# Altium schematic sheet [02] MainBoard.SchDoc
size A3
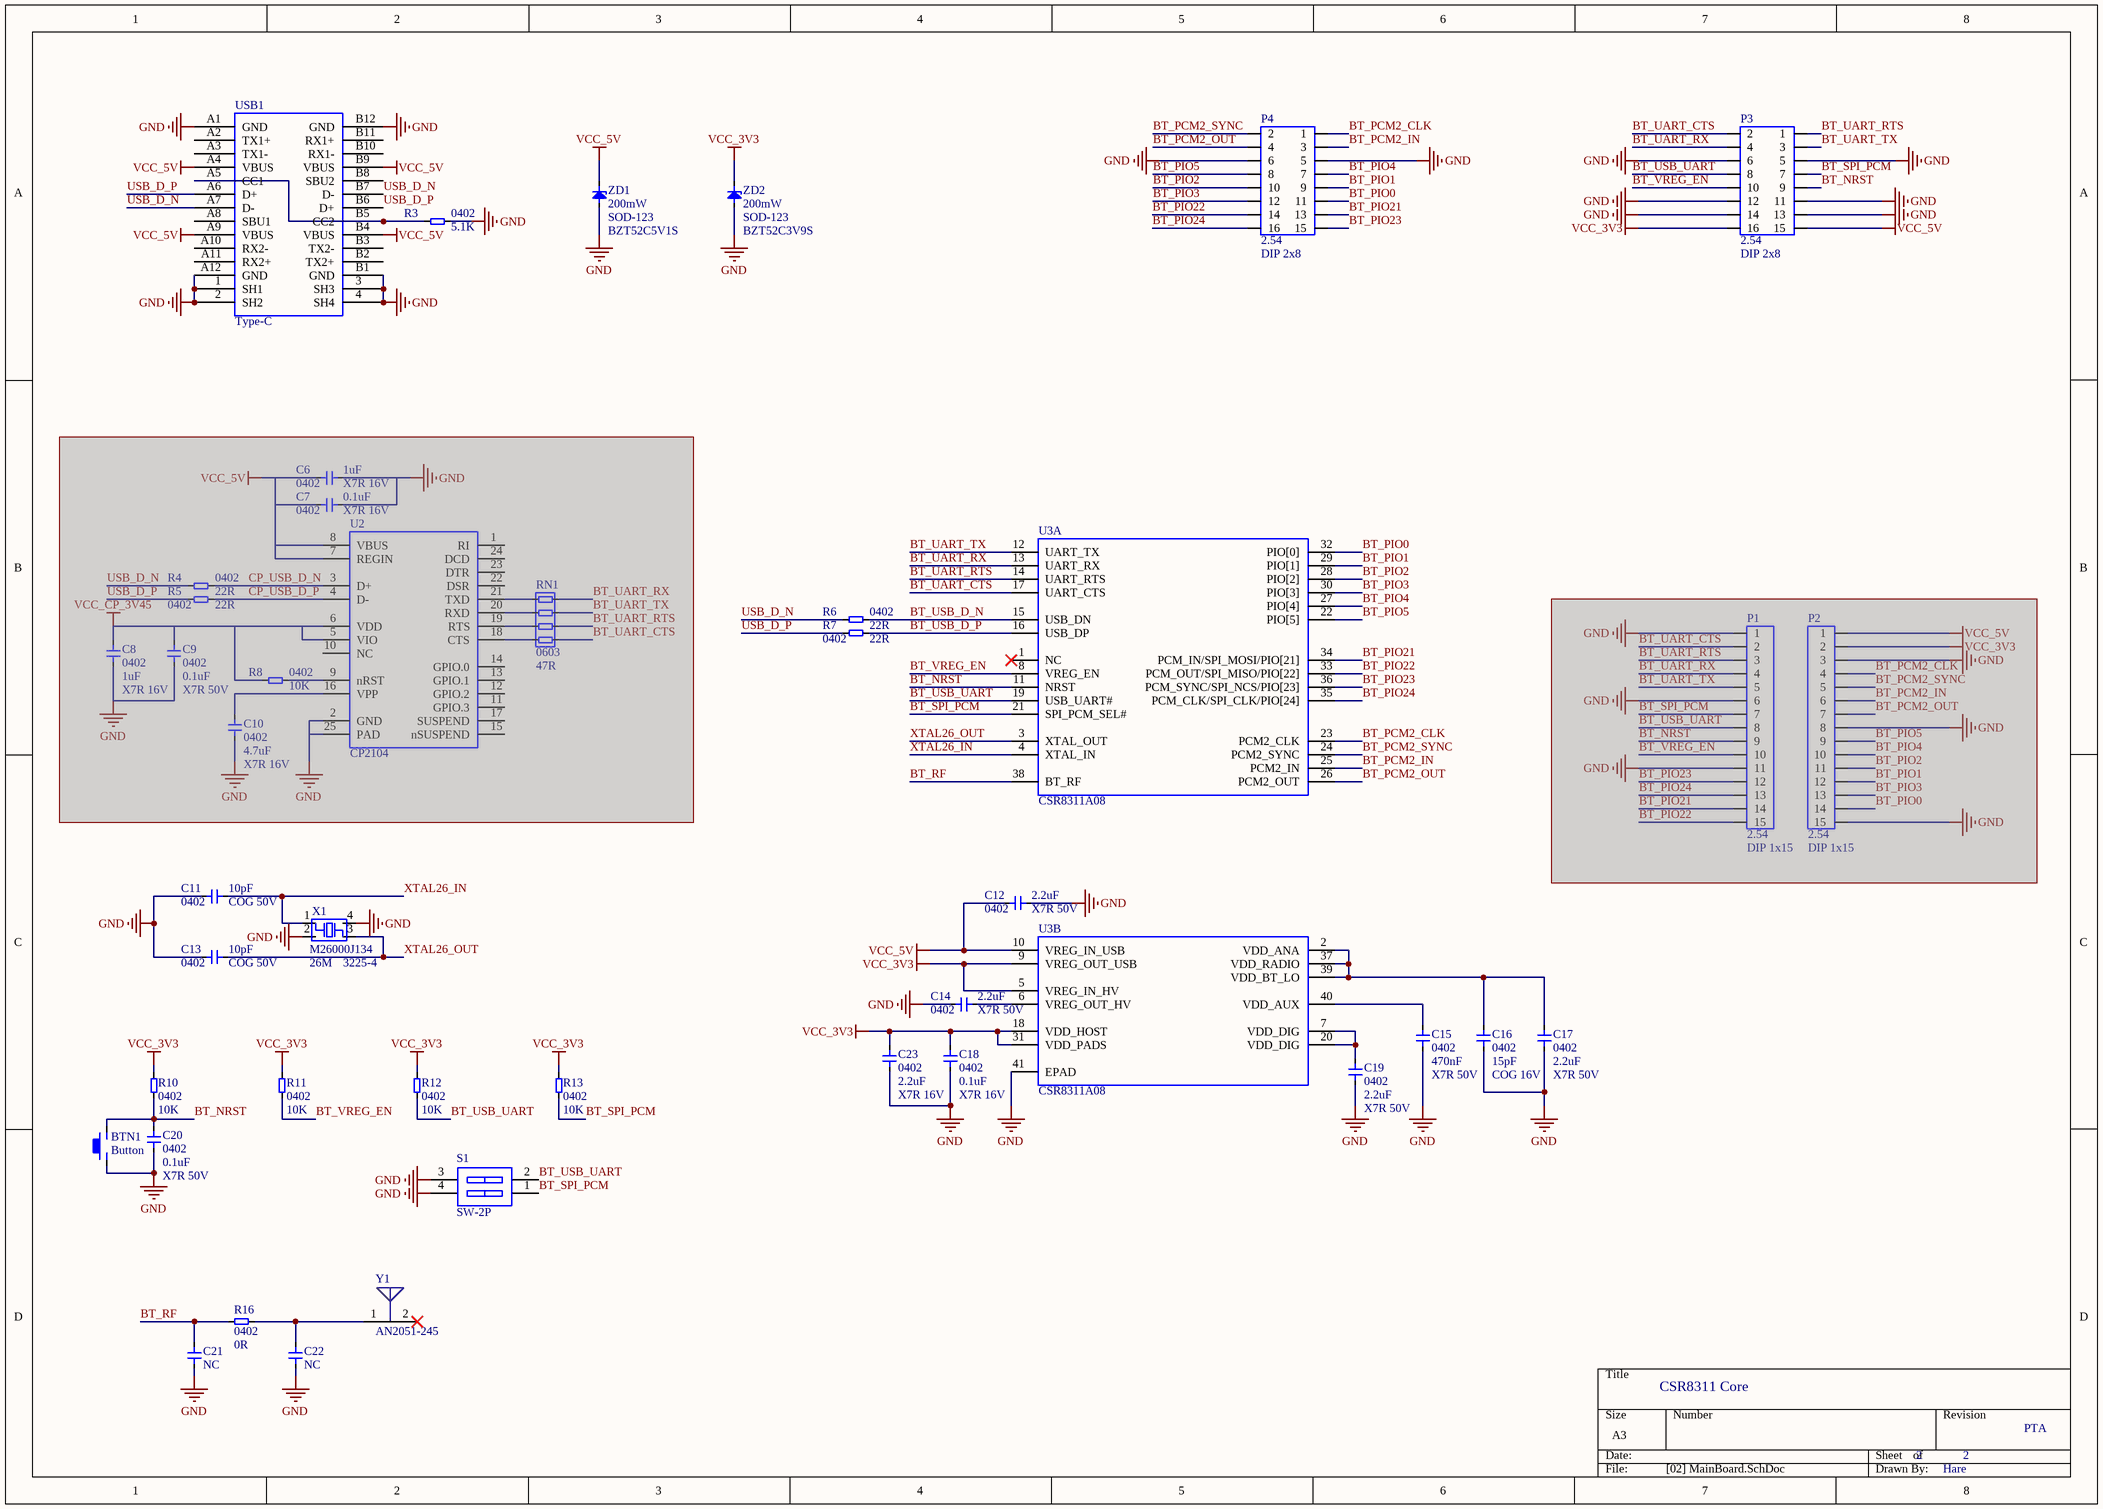
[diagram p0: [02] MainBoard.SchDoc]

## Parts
BTN1  Button  [BTN-4P-4.2*3.4*2.5]
C6  Footprint: 0402  Specification: X7R 16V  [CAP_0402]  (hidden comment: 1uF)  (masked out: inside a compile mask, not in the netlist)
C7  Footprint: 0402  Specification: X7R 16V  [CAP_0402]  (hidden comment: 0.1uF)  (masked out: inside a compile mask, not in the netlist)
C8  Footprint: 0402  Specification: X7R 16V  [CAP_0402]  (hidden comment: 1uF)  (masked out: inside a compile mask, not in the netlist)
C9  Footprint: 0402  Specification: X7R 50V  [CAP_0402]  (hidden comment: 0.1uF)  (masked out: inside a compile mask, not in the netlist)
C10  Footprint: 0402  Specification: X7R 16V  [CAP_0402]  (hidden comment: 4.7uF)  (masked out: inside a compile mask, not in the netlist)
C11  Footprint: 0402  Specification: COG 50V  [CAP_0402]  (hidden comment: 10pF)
C12  Footprint: 0402  Specification: X7R 50V  [CAP_0402]  (hidden comment: 2.2uF)
C13  Footprint: 0402  Specification: COG 50V  [CAP_0402]  (hidden comment: 10pF)
C14  Footprint: 0402  Specification: X7R 50V  [CAP_0402]  (hidden comment: 2.2uF)
C15  Footprint: 0402  Specification: X7R 50V  [CAP_0402]  (hidden comment: 470nF)
C16  Footprint: 0402  Specification: COG 16V  [CAP_0402]  (hidden comment: 15pF)
C17  Footprint: 0402  Specification: X7R 50V  [CAP_0402]  (hidden comment: 2.2uF)
C18  Footprint: 0402  Specification: X7R 16V  [CAP_0402]  (hidden comment: 0.1uF)
C19  Footprint: 0402  Specification: X7R 50V  [CAP_0402]  (hidden comment: 2.2uF)
C20  Footprint: 0402  Specification: X7R 50V  [CAP_0402]  (hidden comment: 0.1uF)
C21  NC  [CAP_0402]
C22  NC  [CAP_0402]
C23  Footprint: 0402  Specification: X7R 16V  [CAP_0402]  (hidden comment: 2.2uF)
P1  Type: 2.54  [HDR1X15_2.54_180]  (hidden comment: DIP 1x15)  (masked out: inside a compile mask, not in the netlist)
P2  Type: 2.54  [HDR1X15_2.54_180]  (hidden comment: DIP 1x15)  (masked out: inside a compile mask, not in the netlist)
P3  Type: 2.54  [HDR2X8_2.54_180]  (hidden comment: DIP 2x8)
P4  Type: 2.54  [HDR2X8_2.54_180]  (hidden comment: DIP 2x8)
R3  Footprint: 0402  [RES_0402]  (hidden comment: 5.1K)
R4  Footprint: 0402  [RES_0402]  (hidden comment: 22R)  (masked out: inside a compile mask, not in the netlist)
R5  Footprint: 0402  [RES_0402]  (hidden comment: 22R)  (masked out: inside a compile mask, not in the netlist)
R6  Footprint: 0402  [RES_0402]  (hidden comment: 22R)
R7  Footprint: 0402  [RES_0402]  (hidden comment: 22R)
R8  Footprint: 0402  [RES_0402]  (hidden comment: 10K)  (masked out: inside a compile mask, not in the netlist)
R10  Footprint: 0402  [RES_0402]  (hidden comment: 10K)
R11  Footprint: 0402  [RES_0402]  (hidden comment: 10K)
R12  Footprint: 0402  [RES_0402]  (hidden comment: 10K)
R13  Footprint: 0402  [RES_0402]  (hidden comment: 10K)
R16  Footprint: 0402  [RES_0402]  (hidden comment: 0R)
RN1  Footprint: 0603  [RES_0402X4]  (hidden comment: 47R)  (masked out: inside a compile mask, not in the netlist)
S1  SW-2P  [SW-SMD-2-1.27]
U2  CP2104  [QFN-24-4.0X4.0-P0.5]  (masked out: inside a compile mask, not in the netlist)
U3  CSR8311A08  [QFN-40-P0.5]  (parts A,B of 2)
USB1  Type-C  [USB-Type-C]
X1  Specification: 26M  Footprint: 3225-4  [XTAL_3225-4]  (hidden comment: M26000J134)
Y1  AN2051-245  [ANT_2.4G_5.1X2.0]
ZD1  Specification: 200mW  [SOD-123]  (hidden comment: BZT52C5V1S)
ZD2  Specification: 200mW  [SOD-123]  (hidden comment: BZT52C3V9S)

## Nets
GND: BTN1.1 C11.1 C12.2 C13.1 C14.1 C15.2 C16.2 C17.2 C18.1 C19.2 C20.2 C21.1 C22.1 C23.2 P3.5 P3.6 P3.11 P3.12 P3.13 P3.14 P4.5 P4.6 R3.1 S1.3(B2) S1.4(B1) U3.41(EPAD) USB1.1(SH1) USB1.2(SH2) USB1.3(SH3) USB1.4(SH4) USB1.A1(GND) USB1.A12(GND) USB1.B1(GND) USB1.B12(GND) X1.2(GND) X1.4(GND) ZD1.1 ZD2.1
VCC_3V3: C18.2 C23.1 P3.16 R10.1 R11.1 R12.1 R13.1 U3.5(VREG_IN_HV) U3.9(VREG_OUT_USB) U3.18(VDD_HOST) U3.31(VDD_PADS) ZD2.2
VCC_5V: C12.1 P3.15 U3.10(VREG_IN_USB) USB1.A4(VBUS) USB1.A9(VBUS) USB1.B4(VBUS) USB1.B9(VBUS) ZD1.2
BT_NRST: BTN1.2 C20.1 P3.9 R10.2 U3.11(NRST)
BT_PCM2_CLK: P4.1 U3.23(PCM2_CLK)
BT_PCM2_IN: P4.3 U3.25(PCM2_IN)
BT_PCM2_OUT: P4.4 U3.26(PCM2_OUT)
BT_PCM2_SYNC: P4.2 U3.24(PCM2_SYNC)
BT_PIO0: P4.11 U3.32(PIO[0])
BT_PIO1: P4.9 U3.29(PIO[1])
BT_PIO2: P4.10 U3.28(PIO[2])
BT_PIO3: P4.12 U3.30(PIO[3])
BT_PIO4: P4.7 U3.27(PIO[4])
BT_PIO5: P4.8 U3.22(PIO[5])
BT_PIO21: P4.13 U3.34(PCM_IN/SPI_MOSI/PIO[21])
BT_PIO22: P4.14 U3.33(PCM_OUT/SPI_MISO/PIO[22])
BT_PIO23: P4.15 U3.36(PCM_SYNC/SPI_NCS/PIO[23])
BT_PIO24: P4.16 U3.35(PCM_CLK/SPI_CLK/PIO[24])
BT_RF: C21.2 R16.1 U3.38(BT_RF)
BT_SPI_PCM: P3.7 R13.2 S1.1(A1) U3.21(SPI_PCM_SEL#)
BT_UART_CTS: P3.2 U3.17(UART_CTS)
BT_UART_RTS: P3.1 U3.14(UART_RTS)
BT_UART_RX: P3.4 U3.13(UART_RX)
BT_UART_TX: P3.3 U3.12(UART_TX)
BT_USB_D_N: R6.1 U3.15(USB_DN)
BT_USB_D_P: R7.1 U3.16(USB_DP)
BT_USB_UART: P3.8 R12.2 S1.2(A2) U3.19(USB_UART#)
BT_VREG_EN: P3.10 R11.2 U3.8(VREG_EN)
USB_D_N: R6.2 USB1.A7(D-) USB1.B7(D-)
USB_D_P: R7.2 USB1.A6(D+) USB1.B6(D+)
XTAL26_IN: C11.2 U3.4(XTAL_IN) X1.1(IN)
XTAL26_OUT: C13.2 U3.3(XTAL_OUT) X1.3(OUT)
NetC14_2: C14.2 U3.6(VREG_OUT_HV)
NetC15_1: C15.1 U3.40(VDD_AUX)
NetC16_1: C16.1 C17.1 U3.2(VDD_ANA) U3.37(VDD_RADIO) U3.39(VDD_BT_LO)
NetC19_1: C19.1 U3.7(VDD_DIG) U3.20(VDD_DIG)
NetC22_2: C22.2 R16.2 Y1.1(FP)
NetR3_2: R3.2 USB1.A5(CC1) USB1.B5(CC2)

Not connected (* = marked no-connect by the designer): U3 1(NC)*; USB1 A2(TX1+) A3(TX1-) A8(SBU1) A10(RX2-) A11(RX2+) B2(TX2+) B3(TX2-) B8(SBU2) B10(RX1-) B11(RX1+); Y1 2(NC)*

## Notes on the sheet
- CSR8311 Core
- 2
- PTA
- Hare

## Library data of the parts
C6-C20 C23 = CAP: Capacitor
C21 C22 = CAP: Capacitor; Specification: X7R 16V
P1 P2 = HDR1x15: Header
P3 P4 = HDR2x8: Header
R3-R8 R10-R13 R16 = RES: Resistor; Specification: ±1%
RN1 = RES-4: Resistor Array; Specification: ±5%
S1 = SW-2P: 拨码开关2P
U2 = CP2104: SINGLE-CHIP USB-TO-UART BRIDGE
U3 = CSR8311: Bluetooth v4.1 single-chip radio and baseband IC for automotive applications.
USB1 = USB-Type-C
X1 = XTAL-4P
Y1 = ANTENNA
ZD1 ZD2 = Diode-ZD: Zender Diode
